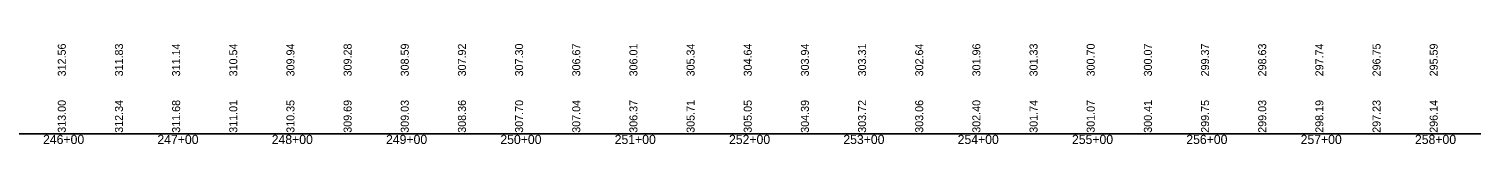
# Model space of a CAD drawing. Extents: x 1838386 to 1955906, y 719739 to 834437.
# Drawn here: x 1902930 to 1904191, y 827954 to 828041 of the extents above; entities that cross this region are included whole.
import ezdxf

# ---------------------------------------------------------------- set-up
doc = ezdxf.new("R2010")
doc.units = 0
for name, color, linetype in [('RD_DDB_StaTX', 7, 'Continuous'), ('RD_DDB_StripGrade', 7, 'Continuous'), ('RD_GPK_Profile_Cell', 7, 'Continuous')]:
    doc.layers.add(name, color=color, linetype=linetype)

msp = doc.modelspace()

# ---------------------------------------------------------------- linework, layer by layer
at = {"layer": 'RD_GPK_Profile_Cell'}
msp.add_line((1878363.1, 827962.8), (1926563.1, 827962.8), dxfattribs=at)

# ---------------------------------------------------------------- texts
at = {"layer": 'RD_DDB_StaTX'}
for s, p in [('246+00', (1902942.2, 827953.8)), ('247+00', (1903042.2, 827953.8)), ('248+00', (1903142.2, 827953.8)), ('249+00', (1903242.2, 827953.8)), ('250+00', (1903342.2, 827953.8)), ('251+00', (1903442.2, 827953.8)), ('252+00', (1903542.2, 827953.8)), ('253+00', (1903642.2, 827953.8)), ('254+00', (1903742.2, 827953.8)), ('255+00', (1903842.2, 827953.8)), ('256+00', (1903942.2, 827953.8)), ('257+00', (1904042.2, 827953.8)), ('258+00', (1904142.2, 827953.8))]:
    msp.add_text(s, height=8, dxfattribs=at).set_placement(p)
at = {"layer": 'RD_DDB_StripGrade'}
for s, p in [('312.56', (1902962.1, 828012.8)), ('311.83', (1903012.1, 828012.8)), ('311.14', (1903062.1, 828012.8)), ('310.54', (1903112.1, 828012.8)), ('309.94', (1903162.1, 828012.8)), ('309.28', (1903212.1, 828012.8)), ('308.59', (1903262.1, 828012.8)), ('307.92', (1903312.1, 828012.8)), ('307.30', (1903362.1, 828012.8)), ('306.67', (1903412.1, 828012.8)), ('306.01', (1903462.1, 828012.8)), ('305.34', (1903512.1, 828012.8)), ('304.64', (1903562.1, 828012.8)), ('303.94', (1903612.1, 828012.8)), ('303.31', (1903662.1, 828012.8)), ('302.64', (1903712.1, 828012.8)), ('301.96', (1903762.1, 828012.8)), ('301.33', (1903812.1, 828012.8)), ('300.70', (1903862.1, 828012.8)), ('300.07', (1903912.1, 828012.8)), ('299.37', (1903962.1, 828012.8)), ('298.63', (1904012.1, 828012.8)), ('297.74', (1904062.1, 828012.8)), ('296.75', (1904112.1, 828012.8)), ('295.59', (1904162.1, 828012.8)), ('313.00', (1902962.1, 827963.6)), ('312.34', (1903012.1, 827963.6)), ('311.68', (1903062.1, 827963.6)), ('311.01', (1903112.1, 827963.6)), ('310.35', (1903162.1, 827963.6)), ('309.69', (1903212.1, 827963.6)), ('309.03', (1903262.1, 827963.6)), ('308.36', (1903312.1, 827963.6)), ('307.70', (1903362.1, 827963.6)), ('307.04', (1903412.1, 827963.6)), ('306.37', (1903462.1, 827963.6)), ('305.71', (1903512.1, 827963.6)), ('305.05', (1903562.1, 827963.6)), ('304.39', (1903612.1, 827963.6)), ('303.72', (1903662.1, 827963.6)), ('303.06', (1903712.1, 827963.6)), ('302.40', (1903762.1, 827963.6)), ('301.74', (1903812.1, 827963.6)), ('301.07', (1903862.1, 827963.6)), ('300.41', (1903912.1, 827963.6)), ('299.75', (1903962.1, 827963.6)), ('299.03', (1904012.1, 827963.6)), ('298.19', (1904062.1, 827963.6)), ('297.23', (1904112.1, 827963.6)), ('296.14', (1904162.1, 827963.6))]:
    msp.add_text(s, height=7, rotation=90, dxfattribs=at).set_placement(p)

doc.saveas('drawing.dxf')
